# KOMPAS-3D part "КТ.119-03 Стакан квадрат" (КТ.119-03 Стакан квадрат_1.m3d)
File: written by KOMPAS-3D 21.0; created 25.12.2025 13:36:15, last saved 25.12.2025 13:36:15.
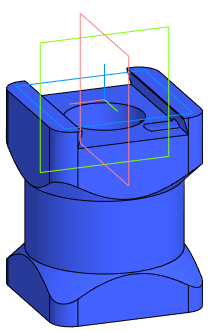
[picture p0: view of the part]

Document properties: Автор: Марсель; Организация: Марсель; Полное имя файла: C:\Users\User\Desktop\Pelorus PRO доработки\ЗАФИКСИРОВАЛИ\Стакан\КТ.119-03 Стакан квадрат_1.m3d

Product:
- Part/product: КТ.119-03 Стакан квадрат
    Комментарий: Марсель

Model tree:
1. Операция без истории:1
